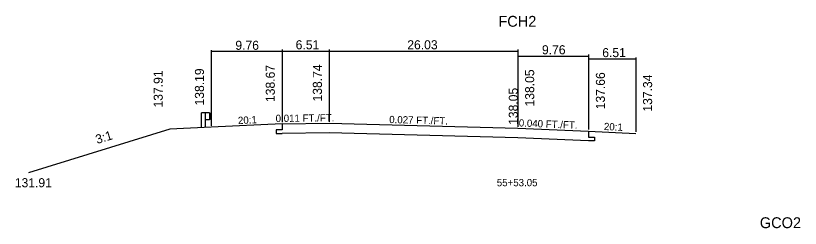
# Model space of a CAD drawing. Extents: x -14327 to 8886, y -10 to 39048.
# Drawn here: x 1069.9 to 1178.1, y 27033.2 to 27062.6 of the extents above; entities that cross this region are included whole.
import ezdxf

# ---------------------------------------------------------------- set-up
doc = ezdxf.new("R2010")
doc.units = 0
doc.layers.add('Level 20', color=7, linetype='Continuous')
doc.layers.add('RD_XS_TX_Baseline', color=7, linetype='Continuous')

msp = doc.modelspace()

# ---------------------------------------------------------------- linework, layer by layer
at = {"layer": 'Level 20'}
for p, q in [((1096.87, 27057.82), (1096.87, 27047.39)), ((1106.63, 27057.62), (1096.87, 27057.62)), ((1106.63, 27057.89), (1106.63, 27047.87)), ((1106.63, 27057.82), (1106.63, 27047.87)), ((1106.63, 27057.69), (1113.13, 27057.69)), ((1113.13, 27057.89), (1113.13, 27047.94)), ((1113.13, 27057.69), (1139.16, 27057.69)), ((1139.16, 27057.89), (1139.16, 27047.25)), ((1139.16, 27057.2), (1139.16, 27047.25)), ((1148.93, 27057.2), (1148.93, 27046.86)), ((1139.16, 27057), (1148.93, 27057)), ((1148.93, 27056.81), (1148.93, 27046.86)), ((1148.93, 27056.61), (1155.43, 27056.61)), ((1155.43, 27056.81), (1155.43, 27046.54)), ((1095.53, 27047.19), (1095.53, 27049.18)), ((1096.08, 27049.18), (1095.53, 27049.18)), ((1096.08, 27047.19), (1096.08, 27049.18)), ((1096.64, 27049.18), (1096.08, 27049.18)), ((1096.64, 27049.18), (1096.64, 27048.21)), ((1096.71, 27049.1), (1096.64, 27049.12)), ((1096.71, 27048.77), (1096.71, 27048.61)), ((1096.84, 27049.01), (1096.73, 27049.1)), ((1096.84, 27048.91), (1096.73, 27048.81)), ((1096.84, 27048.48), (1096.73, 27048.57)), ((1096.64, 27048.21), (1096.08, 27048.21)), ((1096.71, 27048.28), (1096.64, 27048.27)), ((1096.84, 27048.38), (1096.73, 27048.28)), ((1106.63, 27047.67), (1096.87, 27047.19)), ((1106.63, 27047.67), (1113.13, 27047.74)), ((1106.63, 27047.67), (1106.63, 27046.84)), ((1113.13, 27047.74), (1139.16, 27047.05)), ((1091.17, 27046.91), (1071.65, 27040.91)), ((1096.87, 27047.19), (1091.17, 27046.91)), ((1106.63, 27046.84), (1105.81, 27046.83)), ((1105.81, 27046.83), (1105.81, 27046.33)), ((1113.13, 27046.41), (1106.63, 27046.34)), ((1139.16, 27045.72), (1113.13, 27046.41)), ((1139.16, 27047.05), (1148.93, 27046.66)), ((1148.93, 27046.66), (1148.93, 27045.83)), ((1148.93, 27046.66), (1155.43, 27046.34)), ((1105.81, 27046.33), (1106.63, 27046.34)), ((1148.93, 27045.33), (1139.16, 27045.72)), ((1148.93, 27045.83), (1149.74, 27045.81)), ((1149.74, 27045.31), (1148.93, 27045.33)), ((1149.74, 27045.81), (1149.74, 27045.31))]:
    msp.add_line(p, q, dxfattribs=at)
for centre, radius, start, end in [((1096.71, 27049.08), 0.026, 50.9495, 90), ((1096.78, 27048.77), 0.0651, 135, 180), ((1096.78, 27048.61), 0.0651, 180, 237.0105), ((1096.8, 27048.96), 0.0651, 309.0337, 50.9664), ((1096.71, 27048.3), 0.026, 270, 309.0504), ((1096.8, 27048.43), 0.0651, 309.0337, 50.9664)]:
    msp.add_arc(centre, radius, start, end, dxfattribs=at)

# ---------------------------------------------------------------- texts
for s, height, p in [('FCH2', 1.5, (1136.48, 27061.05)), ('9.76', 1.25, (1100.19, 27057.87)), ('6.51', 1.25, (1108.51, 27057.94)), ('26.03', 1.25, (1123.91, 27057.94)), ('9.76', 1.25, (1142.49, 27057.25)), ('6.51', 1.25, (1150.81, 27056.86)), ('131.91', 1.25, (1069.76, 27038.91)), ('55+53.05', 1, (1136.26, 27039.05))]:
    msp.add_text(s, height=height, dxfattribs=at).set_placement(p)
for s, height, rotation, p in [('138.19', 1.25, 90, (1095.86, 27050.19)), ('138.67', 1.25, 90, (1105.63, 27050.67)), ('138.74', 1.25, 90, (1112.13, 27050.74)), ('138.05', 1.25, 90, (1141.42, 27050.05)), ('137.91', 1.25, 90, (1090.17, 27049.91)), ('137.66', 1.25, 90, (1151.18, 27049.66)), ('137.34', 1.25, 90, (1157.69, 27049.34)), (' 138.05', 1.25, 90, (1139.16, 27047.05)), ('20:1', 1, 2.8152, (1100.57, 27047.62)), ('0.011 FT./FT.', 1, 0.6483, (1105.75, 27047.91)), ('0.027 FT./FT.', 1, 358.4788, (1121.41, 27047.77)), ('0.040 FT./FT.', 1, 357.7128, (1139.28, 27047.3)), ('20:1', 1, 357.1848, (1151.02, 27046.81)), ('3:1', 1.25, 17.0843, (1081.12, 27044.87))]:
    msp.add_text(s, height=height, rotation=rotation, dxfattribs=at).set_placement(p)
at = {"layer": 'RD_XS_TX_Baseline'}
msp.add_text('GCO2', height=1.5, dxfattribs=at).set_placement((1172.55, 27033.27))

doc.saveas('drawing.dxf')
